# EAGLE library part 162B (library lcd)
Display a cristalli liquidi tipo 162B Displaytech http://www.displaytech.com.hk/index.htm
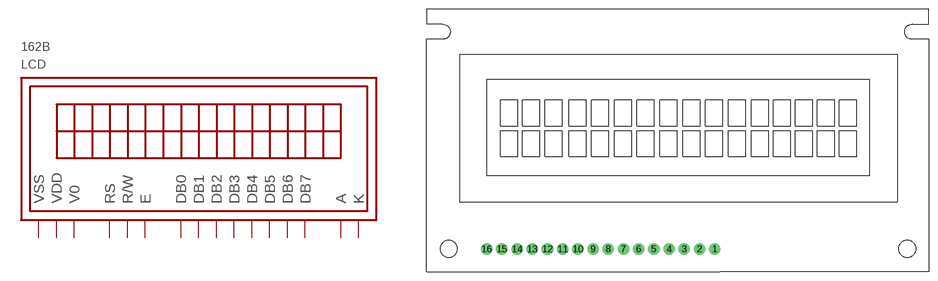
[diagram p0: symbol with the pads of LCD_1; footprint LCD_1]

Designator prefix LCD

## 162B  [LCD_1]
1  A
2  K
3  VSS
4  VDD
5  V0
6  RS
7  R/W
8  E
9  DB0
10  DB1
11  DB2
12  DB3
13  DB4
14  DB5
15  DB6
16  DB7

## Footprint LCD_1 (pad centres in mm)
Display a cristalli liquidi tipo 162B Displaytech Dimensioni 84x44mm
drill 1 pad 1.93 round: 1 0,0; 2 -2.54,0; 3 -5.08,0; 4 -7.62,0; 5 -10.16,0; 6 -12.7,0; 7 -15.24,0; 8 -17.78,0; 9 -20.32,0; 10 -22.86,0; 11 -25.4,0; 12 -27.94,0; 13 -30.48,0; 14 -33.02,0; 15 -35.56,0; 16 -38.1,0
hole 2.8 at -44.418,0
hole 2.8 at 32.163,0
